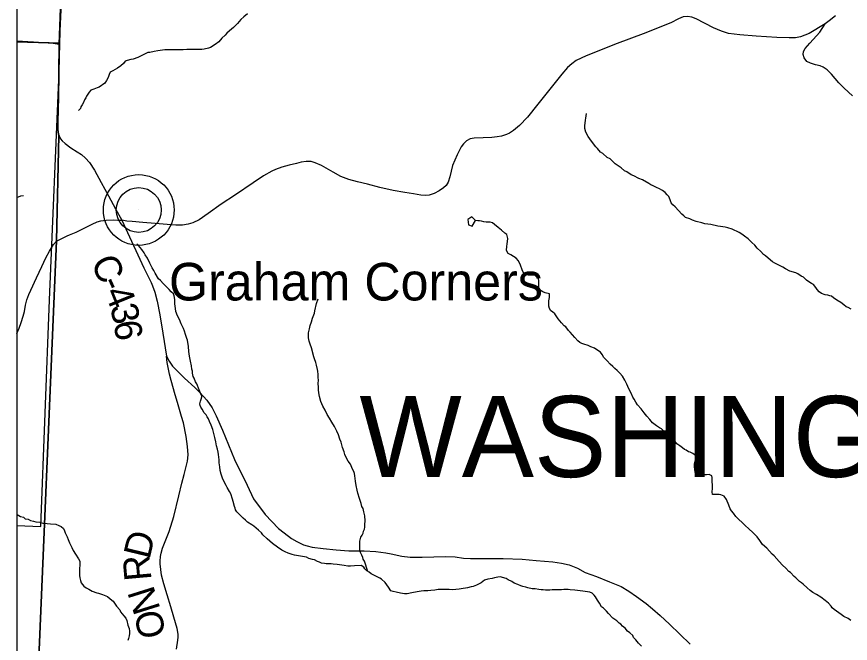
# Model space of a CAD drawing. Extents: x 0 to 34, y 0 to 22.
# Drawn here: x 2.1 to 3.853, y 17.211 to 18.529 of the extents above; entities that cross this region are included whole.
import ezdxf

# ---------------------------------------------------------------- set-up
doc = ezdxf.new("R2010")
doc.units = 0
for name, color, linetype in [('GM_X_Corporation', 7, 'Continuous'), ('GM_X_County_Road', 7, 'Continuous'), ('GM_X_County_Road_Text', 7, 'Continuous'), ('GM_X_Minor_Lake', 7, 'Continuous'), ('GM_X_Minor_River', 7, 'Continuous'), ('GM_X_Township_Road', 7, 'Continuous'), ('GM_X_Township_Text', 7, 'Continuous'), ('GM_X_Unincorporated', 7, 'Continuous'), ('GM_X_Unincorporated_Location', 7, 'Continuous'), ('GM_X_Unincorporated_Text', 7, 'Continuous'), ('SH_Data', 7, 'Continuous')]:
    doc.layers.add(name, color=color, linetype=linetype)

msp = doc.modelspace()

# ---------------------------------------------------------------- linework, layer by layer
at = {"layer": 'GM_X_Corporation'}
for points in [[(8.9, 20.9), (2.1, 20.9), (2.1, 16.4477), (2.1182, 16.4474), (2.1176, 16.4327), (2.1175, 16.4298), (2.1166, 16.4244), (2.1155, 16.4201), (2.2605, 16.4147), (2.3623, 16.41), (2.7707, 16.392), (3.0057, 16.3809), (3.6165, 16.3686), (3.7537, 16.3728), (3.9899, 16.3631), (4.4958, 16.358), (4.9914, 16.3477), (5.6931, 16.3352)], [(2.1, 20.9), (2.1, 16.4477), (2.1182, 16.4474), (2.1195, 16.4774), (2.1214, 16.5347), (2.1408, 17.0483), (2.1838, 18.0574), (2.1889, 18.2792), (2.187, 18.2863), (2.1862, 18.2947), (2.1862, 18.3057), (2.1873, 18.3376), (2.1879, 18.3572), (2.1884, 18.4113), (2.1894, 18.4715), (2.1995, 18.7384)], [(2.1995, 18.7384), (2.1894, 18.4715), (2.1884, 18.4113), (2.1879, 18.3572), (2.1873, 18.3376), (2.1862, 18.3057), (2.1862, 18.2947), (2.187, 18.2863), (2.1889, 18.2792), (2.1838, 18.0574), (2.1408, 17.0483)]]:
    msp.add_lwpolyline(points, dxfattribs=at)
for points in [[(2.1, 19.4892), (2.1, 18.4766), (2.1911, 18.4732), (2.2044, 18.9234), (2.2194, 19.4275), (2.2214, 19.4847)], [(2.1, 18.4766), (2.1, 17.4593), (2.1509, 17.4571), (2.1688, 17.9339), (2.1892, 18.4135), (2.1911, 18.4732)]]:
    msp.add_lwpolyline(points, close=True, dxfattribs=at)
at = {"layer": 'GM_X_County_Road'}
for points in [[(2.2041, 18.8888), (2.2044, 18.8829), (2.204, 18.8571), (2.1997, 18.7378), (2.1985, 18.6923), (2.1935, 18.5576), (2.1896, 18.471), (2.1886, 18.4108), (2.1881, 18.3566), (2.1875, 18.337), (2.1864, 18.3051), (2.1864, 18.2942), (2.1872, 18.2858), (2.1881, 18.2822)], [(3.822, 18.5311), (3.8087, 18.5207), (3.8004, 18.5142), (3.7667, 18.494), (3.7485, 18.4866), (3.7381, 18.4847), (3.725, 18.4847), (3.6989, 18.4852), (3.6556, 18.488), (3.621, 18.491), (3.597, 18.494), (3.5827, 18.4988), (3.5659, 18.5059), (3.5292, 18.5246), (3.5203, 18.5281), (3.5108, 18.5295), (3.5018, 18.5288), (3.492, 18.5247), (3.476, 18.5163), (3.4174, 18.4933), (3.3632, 18.4727), (3.2975, 18.4465), (3.2768, 18.4368), (3.2676, 18.4301), (3.2588, 18.422), (3.2468, 18.4082), (3.1961, 18.345), (3.1744, 18.318), (3.1576, 18.3005), (3.1451, 18.2899), (3.1368, 18.2841), (3.1304, 18.2816), (3.12, 18.2781), (3.1106, 18.2765), (3.0997, 18.2754), (3.0815, 18.2745), (3.0626, 18.2735), (3.0536, 18.2722), (3.046, 18.2682), (3.0398, 18.2618), (3.0349, 18.2556), (3.0264, 18.2383), (3.0169, 18.2159), (3.0114, 18.1922), (3.0073, 18.1811), (3.0033, 18.1739), (2.9976, 18.1689), (2.9888, 18.1626), (2.978, 18.1576), (2.9676, 18.1541), (2.9593, 18.1534), (2.9501, 18.1537), (2.9346, 18.1564), (2.9162, 18.1592), (2.8917, 18.1636), (2.8636, 18.1702), (2.838, 18.1767), (2.8171, 18.1815), (2.7986, 18.1869), (2.782, 18.1931), (2.7656, 18.2025), (2.741, 18.2161), (2.7281, 18.2221), (2.7195, 18.2244), (2.7092, 18.2247), (2.6983, 18.223), (2.6885, 18.2201), (2.6734, 18.2166), (2.658, 18.2129), (2.6441, 18.2076), (2.6368, 18.2044), (2.6192, 18.1947), (2.5976, 18.1795), (2.56, 18.1548), (2.5298, 18.1347), (2.5028, 18.1151), (2.4835, 18.1018), (2.4703, 18.0958), (2.4604, 18.0928), (2.4486, 18.0909), (2.435, 18.0909), (2.4164, 18.0924), (2.3914, 18.0943), (2.3656, 18.0965), (2.3428, 18.0983), (2.3317, 18.0992), (2.3211, 18.1011)], [(2.1881, 18.2822), (2.1891, 18.2786), (2.1925, 18.2726), (2.1958, 18.2681), (2.2017, 18.2626), (2.2139, 18.2536), (2.227, 18.2451), (2.2362, 18.2395), (2.2446, 18.2315), (2.2532, 18.2222), (2.264, 18.2062), (2.2779, 18.1804), (2.2933, 18.1526), (2.3082, 18.1253), (2.3211, 18.1011), (2.3415, 18.0573), (2.3546, 18.0286), (2.3677, 18.0011), (2.3826, 17.9702), (2.3854, 17.9632), (2.3906, 17.9501), (2.3952, 17.9311), (2.401, 17.9019), (2.4074, 17.8638), (2.415, 17.8151), (2.4208, 17.8045), (2.4277, 17.7943), (2.4401, 17.7816), (2.4531, 17.7687), (2.4747, 17.7493), (2.4851, 17.7386), (2.4998, 17.7227), (2.5111, 17.7065), (2.5197, 17.69), (2.5329, 17.6598), (2.5582, 17.5978), (2.585, 17.544), (2.5982, 17.5149), (2.6229, 17.482), (2.6508, 17.4526), (2.6623, 17.4434), (2.6784, 17.432), (2.689, 17.4255), (2.7031, 17.4183), (2.7107, 17.4161), (2.7217, 17.4134), (2.745, 17.4106), (2.7717, 17.4079), (2.7986, 17.4057), (2.831, 17.406), (2.8556, 17.404), (2.8765, 17.4013), (2.8874, 17.3992), (2.9101, 17.3946), (2.9276, 17.3926), (2.9526, 17.3926), (3.0021, 17.3936), (3.0222, 17.3928), (3.0395, 17.3903), (3.0549, 17.3893), (3.0825, 17.3897), (3.1232, 17.3895), (3.1634, 17.3885), (3.1925, 17.3855), (3.2279, 17.3829), (3.2458, 17.3801), (3.2618, 17.3765), (3.2797, 17.3691), (3.2954, 17.36), (3.3197, 17.3516), (3.3472, 17.3405), (3.3713, 17.3305), (3.3873, 17.3211), (3.4034, 17.3098), (3.4243, 17.2949), (3.4374, 17.2837), (3.4538, 17.2696), (3.4731, 17.2516), (3.5167, 17.2094)], [(2.4363, 17.1992), (2.4391, 17.2176), (2.4397, 17.2243), (2.4394, 17.2306), (2.4377, 17.2425), (2.4305, 17.2659), (2.4242, 17.2879), (2.4162, 17.3135), (2.4095, 17.3362), (2.4049, 17.3543), (2.4032, 17.3668), (2.4019, 17.3787), (2.4017, 17.3843), (2.4024, 17.3941), (2.4038, 17.4006), (2.4068, 17.411), (2.4206, 17.4461), (2.4309, 17.4779), (2.4414, 17.5212), (2.4474, 17.5482), (2.452, 17.5663), (2.4591, 17.5942), (2.4607, 17.6079), (2.4594, 17.6254), (2.4564, 17.6462), (2.4508, 17.6747), (2.4466, 17.688), (2.4383, 17.7177), (2.4335, 17.734), (2.425, 17.764), (2.4213, 17.7773), (2.4165, 17.8017), (2.415, 17.8151)]]:
    msp.add_lwpolyline(points, dxfattribs=at)
at = {"layer": 'GM_X_Minor_Lake'}
for points in [[(3.065, 18.1003), (3.0574, 18.1082), (3.049, 18.1025)], [(3.049, 18.1025), (3.0502, 18.0911), (3.0582, 18.0889), (3.065, 18.1003)]]:
    msp.add_lwpolyline(points, dxfattribs=at)
at = {"layer": 'GM_X_Minor_River'}
for points in [[(2.5854, 18.5351), (2.5779, 18.529), (2.5714, 18.5233), (2.5646, 18.5149), (2.5563, 18.5062), (2.5476, 18.4997), (2.542, 18.4944), (2.5382, 18.4906), (2.5318, 18.4838), (2.5253, 18.4765), (2.5178, 18.4705), (2.508, 18.4644), (2.5038, 18.4628), (2.4943, 18.4609), (2.4894, 18.4605), (2.4792, 18.4601), (2.4746, 18.4605), (2.4636, 18.4605), (2.4576, 18.4601), (2.45, 18.4593), (2.4424, 18.4593), (2.4386, 18.4597), (2.4314, 18.4593), (2.4265, 18.4596), (2.4166, 18.4592), (2.4113, 18.4592), (2.4015, 18.4581), (2.3969, 18.4573), (2.389, 18.4562), (2.3799, 18.4539), (2.3761, 18.4535), (2.372, 18.4516), (2.3644, 18.4481), (2.3591, 18.4451), (2.3546, 18.4436), (2.3451, 18.4401), (2.3398, 18.4394), (2.3322, 18.4367), (2.328, 18.4356), (2.325, 18.4306), (2.319, 18.4257), (2.3118, 18.4211), (2.3023, 18.4154), (2.2963, 18.4123), (2.2944, 18.4074), (2.2922, 18.4013), (2.2891, 18.3953), (2.2854, 18.3892), (2.2733, 18.3808), (2.2691, 18.3793), (2.2623, 18.3766), (2.2562, 18.3743), (2.2525, 18.3705), (2.2498, 18.366), (2.2468, 18.3622), (2.2457, 18.3584), (2.243, 18.3542), (2.2404, 18.3485), (2.2378, 18.344), (2.2351, 18.3398), (2.234, 18.336), (2.2298, 18.3318)], [(3.6194, 18.0756), (3.6156, 18.0775), (3.6091, 18.0805), (3.6046, 18.0824), (3.5959, 18.0854), (3.5902, 18.0862), (3.5807, 18.088), (3.575, 18.0888), (3.5598, 18.0918), (3.5473, 18.0937), (3.5409, 18.0959), (3.5291, 18.0985), (3.5212, 18.1012), (3.5159, 18.1042), (3.5071, 18.1068), (3.503, 18.1102), (3.4988, 18.114), (3.4923, 18.1212), (3.4847, 18.1292), (3.4801, 18.1333), (3.4767, 18.1375), (3.4744, 18.1443), (3.4714, 18.1508), (3.4683, 18.1546), (3.4642, 18.1591), (3.4585, 18.1636), (3.4509, 18.1678), (3.4471, 18.1689), (3.4391, 18.1735), (3.4338, 18.1753), (3.4296, 18.178), (3.4163, 18.1859), (3.4087, 18.1886), (3.3981, 18.1946), (3.3924, 18.1965), (3.3833, 18.2029), (3.3784, 18.2052), (3.3715, 18.2112), (3.3674, 18.2139), (3.359, 18.2199), (3.3484, 18.2302), (3.3423, 18.2332), (3.3328, 18.2411), (3.3282, 18.2442), (3.3218, 18.2521), (3.318, 18.2551), (3.3092, 18.2673), (3.302, 18.2771), (3.297, 18.2862), (3.2947, 18.2938), (3.2947, 18.2995), (3.2962, 18.3112), (3.2973, 18.3158), (3.2984, 18.3256)], [(2.1, 18.1492), (2.1084, 18.1522), (2.1141, 18.1533)], [(3.5003, 17.6225), (3.4946, 17.6263), (3.4889, 17.6308), (3.4851, 17.6354), (3.4771, 17.6437), (3.4733, 17.6463), (3.4668, 17.6535), (3.4627, 17.6558), (3.4562, 17.6622), (3.452, 17.6645), (3.4456, 17.6687), (3.4376, 17.6751), (3.4315, 17.6819), (3.4254, 17.6891), (3.4197, 17.6963), (3.4133, 17.7046), (3.4056, 17.7126), (3.4022, 17.7183), (3.3988, 17.7247), (3.3961, 17.7292), (3.3923, 17.7372), (3.3877, 17.7463), (3.3835, 17.7562), (3.379, 17.7649), (3.374, 17.7732), (3.3687, 17.7796), (3.3634, 17.7853), (3.3584, 17.7891), (3.3539, 17.7936), (3.3482, 17.7986), (3.3417, 17.805), (3.3352, 17.8122), (3.3314, 17.8186), (3.328, 17.8235), (3.3204, 17.8288), (3.3151, 17.8322), (3.3079, 17.8345), (3.3018, 17.8375), (3.2931, 17.8402), (3.2885, 17.8421), (3.2848, 17.8439), (3.2806, 17.8473), (3.2737, 17.8545), (3.2642, 17.8655), (3.2604, 17.8689), (3.2551, 17.8765), (3.2513, 17.8788), (3.246, 17.8856), (3.2391, 17.8939), (3.2349, 17.9), (3.2319, 17.9045), (3.2273, 17.9083), (3.2232, 17.9106), (3.2205, 17.9155), (3.2193, 17.9204), (3.219, 17.9253), (3.2193, 17.9318), (3.2208, 17.9382), (3.2208, 17.9462), (3.2113, 17.9481), (3.2068, 17.9504), (3.203, 17.9526), (3.1988, 17.9572), (3.198, 17.9613), (3.198, 17.9735), (3.1976, 17.9784), (3.1968, 17.9879), (3.1926, 17.9867), (3.1881, 17.9856), (3.1839, 17.9852), (3.1763, 17.9852), (3.1722, 17.9871), (3.1661, 17.9905), (3.163, 17.9969), (3.1596, 18.0068), (3.1554, 18.0155), (3.1505, 18.0215), (3.1451, 18.0249), (3.1394, 18.028), (3.1341, 18.031), (3.1303, 18.0371), (3.1307, 18.0462), (3.1318, 18.0507), (3.1329, 18.0628), (3.131, 18.0708), (3.1268, 18.0738), (3.1196, 18.0803), (3.1127, 18.0859), (3.1051, 18.092), (3.1006, 18.0954), (3.0957, 18.0969), (3.0877, 18.0973), (3.0824, 18.098), (3.0778, 18.0991), (3.0737, 18.0999), (3.0699, 18.0999), (3.065, 18.1003)], [(3.8552, 17.9138), (3.8487, 17.9175), (3.8449, 17.9187), (3.84, 17.9228), (3.8332, 17.9278), (3.8248, 17.9327), (3.818, 17.9376), (3.8142, 17.941), (3.8104, 17.9421), (3.8062, 17.9436), (3.8005, 17.9444), (3.7926, 17.947), (3.7876, 17.9508), (3.7838, 17.9553), (3.7808, 17.9595), (3.7762, 17.9656), (3.772, 17.9682), (3.7682, 17.9701), (3.7614, 17.975), (3.7549, 17.9814), (3.75, 17.9837), (3.7432, 17.9886), (3.739, 17.9901), (3.7265, 17.9939), (3.717, 17.9988), (3.7117, 18.0022), (3.695, 18.0105), (3.6901, 18.0135), (3.6859, 18.0173), (3.6749, 18.0264), (3.6707, 18.0291), (3.665, 18.0355), (3.6578, 18.0423), (3.6524, 18.0484), (3.646, 18.0544), (3.6384, 18.0616), (3.6308, 18.0677), (3.6255, 18.0714), (3.6194, 18.0756)], [(2.5169, 17.644), (2.5154, 17.6497), (2.5142, 17.655), (2.5127, 17.6607), (2.5089, 17.6698), (2.5058, 17.6777), (2.5035, 17.6834), (2.5009, 17.6876), (2.4986, 17.6921), (2.4944, 17.6959), (2.4902, 17.7035), (2.4872, 17.7077), (2.486, 17.7115), (2.4853, 17.7152), (2.4864, 17.7206), (2.4879, 17.7244), (2.4898, 17.7297), (2.489, 17.7335), (2.4867, 17.7372), (2.484, 17.7441), (2.4791, 17.7573), (2.4764, 17.7611), (2.4733, 17.7687), (2.4714, 17.7725), (2.4699, 17.7793), (2.4695, 17.7835), (2.4687, 17.7877), (2.468, 17.7945), (2.4657, 17.8043), (2.4649, 17.8081), (2.4637, 17.815), (2.4622, 17.8248), (2.4614, 17.8358), (2.4591, 17.8487), (2.4579, 17.8525), (2.4553, 17.8605), (2.453, 17.868), (2.451, 17.873), (2.4488, 17.8775), (2.4461, 17.8832), (2.4423, 17.8923), (2.4385, 17.8999), (2.435, 17.909), (2.4331, 17.9207), (2.4327, 17.9245), (2.4327, 17.9344), (2.4315, 17.9423), (2.4296, 17.9461), (2.4247, 17.9503), (2.4205, 17.9552), (2.4152, 17.9609), (2.4079, 17.9681), (2.4022, 17.9741), (2.3984, 17.9779), (2.3916, 17.9897), (2.3885, 17.995), (2.3851, 18.001), (2.3801, 18.0109), (2.3752, 18.0211), (2.3702, 18.0283), (2.3679, 18.0328), (2.3634, 18.0393), (2.3596, 18.0434), (2.3565, 18.0476), (2.3527, 18.051)], [(2.8384, 17.3625), (2.8315, 17.3841), (2.8288, 17.3882), (2.828, 17.392), (2.8257, 17.3966), (2.8234, 17.4019), (2.8219, 17.4068), (2.8215, 17.4129), (2.8219, 17.4212), (2.8219, 17.4261), (2.8241, 17.4345), (2.8264, 17.4387), (2.8286, 17.4432), (2.8298, 17.447), (2.8313, 17.4512), (2.832, 17.4554), (2.8324, 17.4614), (2.8327, 17.469), (2.8323, 17.4793), (2.83, 17.4876), (2.8285, 17.4948), (2.8258, 17.499), (2.8243, 17.5054), (2.8208, 17.5157), (2.8178, 17.527), (2.8162, 17.5331), (2.8143, 17.543), (2.8128, 17.5524), (2.8112, 17.5638), (2.8104, 17.5687), (2.8089, 17.5725), (2.8066, 17.5778), (2.802, 17.5881), (2.7975, 17.5945), (2.7933, 17.6021), (2.7902, 17.6081), (2.7887, 17.6142), (2.7856, 17.6233), (2.7837, 17.6286), (2.7822, 17.6343), (2.7799, 17.6407), (2.7768, 17.6495), (2.7734, 17.6574), (2.7685, 17.6673), (2.7631, 17.6764), (2.7578, 17.6847), (2.7528, 17.6927), (2.7486, 17.7014), (2.7437, 17.7101), (2.7395, 17.7196), (2.7372, 17.7302), (2.7364, 17.734), (2.7349, 17.7434), (2.7345, 17.7487), (2.7344, 17.7594), (2.7348, 17.7635), (2.7344, 17.7715), (2.7344, 17.7764), (2.7336, 17.7833), (2.7328, 17.7871), (2.7305, 17.7965), (2.729, 17.8015), (2.7267, 17.8098), (2.7252, 17.814), (2.7198, 17.8325), (2.7171, 17.8405), (2.7149, 17.8469), (2.7137, 17.8538), (2.714, 17.864), (2.7159, 17.8727), (2.717, 17.8799), (2.72, 17.8872), (2.7223, 17.8948), (2.7264, 17.9058), (2.7268, 17.9103), (2.7305, 17.9262), (2.7343, 17.9354)], [(3.0669, 17.3337), (3.0601, 17.331), (3.0559, 17.3299), (3.0484, 17.3276), (3.0351, 17.3257), (3.0306, 17.3249), (3.0237, 17.3241), (3.0158, 17.3237), (3.0097, 17.3241), (3.0033, 17.3245), (2.998, 17.3245), (2.9904, 17.3241), (2.9866, 17.3244), (2.9798, 17.3229), (2.9711, 17.3221), (2.9646, 17.3214), (2.9567, 17.3213), (2.9506, 17.3209), (2.9423, 17.3194), (2.9313, 17.3171), (2.9211, 17.3156), (2.9158, 17.3156), (2.9074, 17.3167), (2.898, 17.3186), (2.8919, 17.3201), (2.8873, 17.3216), (2.882, 17.3292), (2.8786, 17.3341), (2.8748, 17.3394), (2.8676, 17.3462), (2.8638, 17.3485), (2.8569, 17.3519), (2.8497, 17.3549), (2.8456, 17.3571), (2.8414, 17.3606), (2.8368, 17.3636), (2.8323, 17.3677), (2.83, 17.3715), (2.8243, 17.3746), (2.8103, 17.3745), (2.8019, 17.3737), (2.7962, 17.3737), (2.789, 17.3749), (2.7792, 17.3764), (2.7743, 17.3767), (2.7659, 17.3775), (2.7614, 17.3782), (2.7549, 17.3786), (2.7511, 17.3786), (2.7474, 17.379), (2.7409, 17.3801), (2.7367, 17.382), (2.7329, 17.3831), (2.7265, 17.3865), (2.7223, 17.3876), (2.7147, 17.3895), (2.7094, 17.3921), (2.6969, 17.3944), (2.6927, 17.3955), (2.6844, 17.3966), (2.6795, 17.3982), (2.6711, 17.4008), (2.6647, 17.4034), (2.6575, 17.4068), (2.6487, 17.4133), (2.6381, 17.4212), (2.6271, 17.4307), (2.618, 17.4394), (2.6149, 17.4435), (2.6088, 17.4492), (2.599, 17.4575), (2.5948, 17.4606), (2.5857, 17.4659), (2.5811, 17.4704), (2.5762, 17.4746), (2.5712, 17.4791), (2.5667, 17.484), (2.5629, 17.4878), (2.5602, 17.4916), (2.5594, 17.4954), (2.5583, 17.4992), (2.5556, 17.5098), (2.5541, 17.5147), (2.5503, 17.5257), (2.5476, 17.5307), (2.5426, 17.539), (2.5403, 17.5432), (2.5369, 17.5492), (2.5327, 17.5587), (2.53, 17.567), (2.5281, 17.5746), (2.527, 17.5822), (2.5258, 17.5905), (2.5258, 17.597), (2.525, 17.6027), (2.5246, 17.608), (2.5238, 17.6133), (2.5223, 17.6197), (2.52, 17.6269), (2.5188, 17.6353), (2.5169, 17.644)], [(3.8545, 17.2591), (3.8492, 17.2633), (3.8401, 17.2678), (3.8344, 17.272), (3.8196, 17.2822), (3.8154, 17.2856), (3.8131, 17.2894), (3.8078, 17.2954), (3.8006, 17.3015), (3.7915, 17.3083), (3.7824, 17.3136), (3.7748, 17.3181), (3.7691, 17.3223), (3.763, 17.3276), (3.7543, 17.3355), (3.7505, 17.3382), (3.7467, 17.3412), (3.7391, 17.3488), (3.7353, 17.3518), (3.7277, 17.3598), (3.7239, 17.3624), (3.7178, 17.3692), (3.7109, 17.3753), (3.7037, 17.3836), (3.6931, 17.395), (3.6889, 17.3984), (3.6779, 17.4112), (3.6684, 17.4192), (3.663, 17.4271), (3.6577, 17.4351), (3.6486, 17.4446), (3.6402, 17.4517), (3.6322, 17.4589), (3.6129, 17.4782), (3.6075, 17.4847), (3.6037, 17.49), (3.6007, 17.4938), (3.5976, 17.5021), (3.5927, 17.5135), (3.5881, 17.521), (3.5813, 17.5237), (3.5775, 17.5241), (3.571, 17.5244), (3.5638, 17.5244), (3.5631, 17.5297), (3.5638, 17.5369), (3.5634, 17.5411), (3.5634, 17.5449), (3.563, 17.5502), (3.5626, 17.5551), (3.5626, 17.5597), (3.5622, 17.5635), (3.5565, 17.5661), (3.5508, 17.5657), (3.547, 17.5657), (3.541, 17.5653), (3.5292, 17.5642), (3.527, 17.571), (3.5262, 17.5767), (3.5258, 17.5824), (3.5258, 17.5877), (3.5273, 17.5941), (3.5291, 17.6021), (3.5276, 17.6059), (3.5219, 17.6104), (3.5166, 17.6131), (3.5128, 17.6138), (3.5082, 17.6172), (3.5044, 17.6191), (3.5003, 17.6225)], [(2.1, 17.4823), (2.101, 17.482), (2.1078, 17.4782), (2.1143, 17.4763), (2.1181, 17.4733), (2.1245, 17.4721), (2.1291, 17.4695), (2.1355, 17.4684), (2.1404, 17.4669), (2.1484, 17.4661), (2.1552, 17.4642), (2.1643, 17.4635), (2.1715, 17.4628), (2.1821, 17.4616), (2.1886, 17.459), (2.1939, 17.4571), (2.1988, 17.4529), (2.2004, 17.4476), (2.2023, 17.4438), (2.2061, 17.4355), (2.208, 17.4298), (2.2114, 17.4222), (2.213, 17.4181), (2.216, 17.4128), (2.2191, 17.4067), (2.224, 17.3984), (2.2301, 17.3889), (2.2331, 17.384), (2.2328, 17.3779), (2.2321, 17.3661), (2.2321, 17.354), (2.2329, 17.3491), (2.2344, 17.3434), (2.2359, 17.3385), (2.2416, 17.3316), (2.2462, 17.3282), (2.2519, 17.3248), (2.2591, 17.3211), (2.2686, 17.3177), (2.2724, 17.3165), (2.2803, 17.3139), (2.2841, 17.3124), (2.291, 17.3097), (2.297, 17.3048), (2.3027, 17.2995), (2.31, 17.2893), (2.3172, 17.2813), (2.3183, 17.2776), (2.3252, 17.2692), (2.3298, 17.2643), (2.3317, 17.259), (2.334, 17.2491), (2.3363, 17.2423), (2.337, 17.237), (2.3371, 17.2321), (2.3363, 17.2271), (2.3352, 17.2211), (2.3341, 17.2169)], [(3.4144, 17.2055), (3.4079, 17.2115), (3.4022, 17.2183), (3.3973, 17.2236), (3.3961, 17.2274), (3.39, 17.2331), (3.3847, 17.2369), (3.3802, 17.2429), (3.3741, 17.2471), (3.371, 17.2516), (3.3672, 17.2539), (3.3627, 17.2585), (3.3581, 17.2611), (3.354, 17.2641), (3.3448, 17.274), (3.3403, 17.2785), (3.3346, 17.285), (3.3304, 17.288), (3.3258, 17.2959), (3.322, 17.3016), (3.3174, 17.3088), (3.3148, 17.3126), (3.3106, 17.3164), (3.3057, 17.3187), (3.2958, 17.3205), (3.2909, 17.3209), (3.2799, 17.322), (3.2742, 17.3228), (3.2644, 17.3239), (3.2602, 17.3242), (3.2511, 17.3242), (3.2462, 17.3235), (3.2356, 17.3234), (3.2261, 17.3238), (3.2212, 17.323), (3.2124, 17.323), (3.2075, 17.3234), (3.2034, 17.3237), (3.198, 17.3245), (3.1905, 17.3256), (3.1844, 17.326), (3.1753, 17.3279), (3.1707, 17.329), (3.1643, 17.3309), (3.1601, 17.332), (3.1541, 17.3346), (3.1465, 17.3377), (3.1415, 17.3414), (3.1339, 17.3445), (3.1294, 17.3475), (3.1173, 17.3509), (3.1123, 17.3505), (3.1048, 17.349), (3.1002, 17.3478), (3.0911, 17.3459), (3.0843, 17.344), (3.0768, 17.3383), (3.0669, 17.3337)]]:
    msp.add_lwpolyline(points, dxfattribs=at)
at = {"layer": 'GM_X_Township_Road'}
for points in [[(3.8578, 18.363), (3.8405, 18.3789), (3.8292, 18.3902), (3.8137, 18.4084), (3.8048, 18.4174), (3.7965, 18.4227), (3.7898, 18.4257), (3.7803, 18.4282), (3.7697, 18.4312), (3.7623, 18.4352), (3.7566, 18.4423), (3.7543, 18.4495), (3.7547, 18.4561), (3.7586, 18.4626), (3.7681, 18.4737), (3.7891, 18.4965), (3.8004, 18.5142)], [(2.1896, 18.471), (2.1771, 18.4727), (2.1354, 18.4758), (2.1, 18.4775)], [(2.2113, 18.0705), (2.2248, 18.076), (2.2418, 18.0844), (2.2585, 18.093), (2.2693, 18.0977), (2.2773, 18.0998), (2.2884, 18.1011), (2.3042, 18.1017), (2.3129, 18.1014), (2.3211, 18.1011)], [(2.1, 17.8626), (2.1053, 17.8742), (2.1097, 17.886), (2.1138, 17.8991), (2.1162, 17.909), (2.1185, 17.9222), (2.1217, 17.9335), (2.1256, 17.9452), (2.1295, 17.954), (2.1417, 17.9798), (2.1528, 18.004), (2.1611, 18.0222), (2.1687, 18.0359), (2.1773, 18.0497), (2.1841, 18.0569), (2.2059, 18.0683), (2.2113, 18.0705)]]:
    msp.add_lwpolyline(points, dxfattribs=at)
at = {"layer": 'GM_X_Unincorporated'}
for radius in [0.0744, 0.0472]:
    msp.add_circle((2.3568, 18.1226), radius, dxfattribs=at)
at = {"layer": 'GM_X_Unincorporated_Location'}
msp.add_line((2.3568, 18.1226), (2.3568, 18.1226), dxfattribs=at)
at = {"layer": 'SH_Data'}
msp.add_line((2.1, 20.9), (2.1, 14.1), dxfattribs=at)

# ---------------------------------------------------------------- texts
at = {"layer": 'GM_X_County_Road_Text'}
for s, rotation, p in [('C', 294.6901, (2.2549, 18.0127)), ('-', 294.5363, (2.2743, 17.9703)), ('4', 292.1319, (2.2838, 17.9497)), ('3', 282.5, (2.2962, 17.9197)), ('6', 278.9875, (2.3036, 17.8864)), ('D', 76.4727, (2.3793, 17.3865)), ('R', 95.1277, (2.3838, 17.3449)), ('N', 107.4002, (2.4028, 17.2834)), ('O', 100.8003, (2.4139, 17.2274))]:
    msp.add_text(s, height=0.0568, rotation=rotation, dxfattribs=at).set_placement(p)
at = {"layer": 'GM_X_Township_Text'}
msp.add_text('WASHINGTON', height=0.17045, rotation=0, dxfattribs=at).set_placement((2.821, 17.5609))
at = {"layer": 'GM_X_Unincorporated_Text'}
msp.add_text('Graham Corners', height=0.078977, rotation=0, dxfattribs=at).set_placement((2.4204, 17.9323))

doc.saveas('drawing.dxf')
